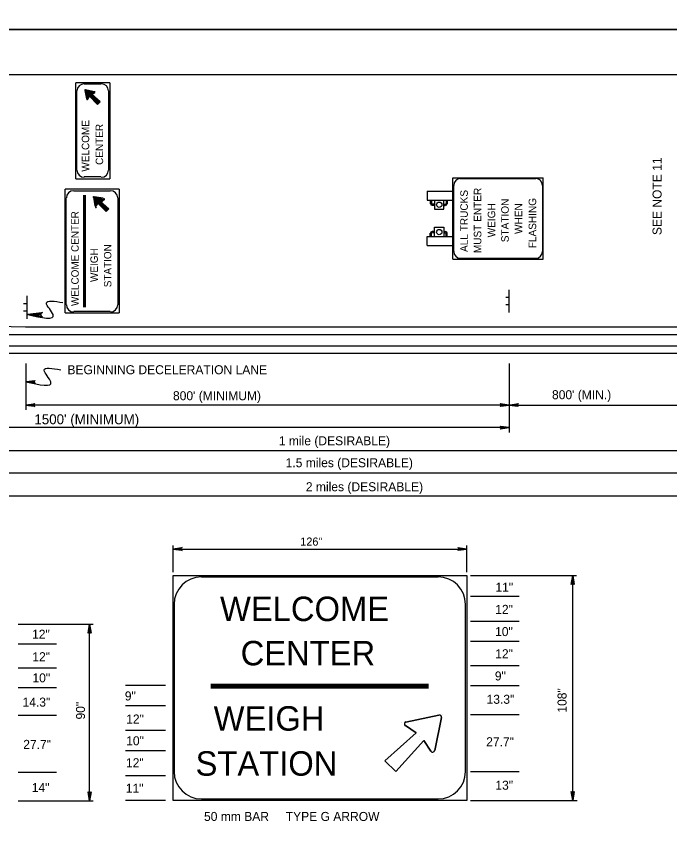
# Model space of a CAD drawing. Extents: x 2189973 to 2192941, y 2147557 to 2151454.
# Drawn here: x 2191176 to 2191890, y 2148636 to 2149520 of the extents above; entities that cross this region are included whole.
import ezdxf

# ---------------------------------------------------------------- set-up
doc = ezdxf.new("R2010")
doc.units = 0
for name, color, linetype in [('Default', 7, 'Continuous'), ('Level 2', 7, 'Continuous'), ('PLT-BNDY', 7, 'Continuous')]:
    doc.layers.add(name, color=color, linetype=linetype)

# ---------------------------------------------------------------- blocks, each defined once
blk = doc.blocks.new('RARROW')
at = {"layer": 'Default'}
blk.add_lwpolyline([(-18.156, 2.28), (-17.479, 0.966), (0, 0), (-18.156, 2.28), (-19.086, 3.077), (0, 0), (-17.465, -0.864), (-18.103, -2.164), (0, 0), (-19.086, -3.033), (-18.103, -2.164)], dxfattribs=at)

msp = doc.modelspace()

# ---------------------------------------------------------------- linework, layer by layer
at = {"layer": 'Default'}
for p, q in [((2190104.48, 2149456.38), (2192683.21, 2149456.38)), ((2191241.29, 2149342.37), (2191241.29, 2149447.36)), ((2191278.61, 2149447.36), (2191241.29, 2149447.36)), ((2191250.72, 2149446.13), (2191268.77, 2149446.13)), ((2191251.13, 2149439.57), (2191251.13, 2149439.57)), ((2191261.79, 2149437.52), (2191251.95, 2149439.57)), ((2191278.61, 2149447.36), (2191278.61, 2149342.37)), ((2191242.52, 2149351.81), (2191242.52, 2149438.34)), ((2191251.13, 2149438.75), (2191253.18, 2149429.73)), ((2191254.41, 2149429.32), (2191256.46, 2149432.6)), ((2191256.46, 2149432.6), (2191256.46, 2149432.6)), ((2191256.46, 2149432.6), (2191265.07, 2149423.57)), ((2191257.69, 2149433.42), (2191257.69, 2149433.42)), ((2191258.92, 2149434.65), (2191262.2, 2149436.7)), ((2191258.92, 2149434.65), (2191262.2, 2149436.7)), ((2191258.92, 2149434.65), (2191258.92, 2149434.65)), ((2191267.95, 2149426.44), (2191258.92, 2149434.65)), ((2191263.43, 2149437.52), (2191263.43, 2149437.52)), ((2191276.97, 2149438.34), (2191276.97, 2149351.81)), ((2191253.59, 2149428.09), (2191253.59, 2149428.09)), ((2191265.07, 2149423.57), (2191267.95, 2149426.44)), ((2191265.07, 2149423.57), (2191265.07, 2149423.57)), ((2191267.95, 2149426.44), (2191267.95, 2149426.44)), ((2191241.29, 2149342.37), (2191278.61, 2149342.37)), ((2191268.77, 2149344.42), (2191250.72, 2149344.42)), ((2191229.81, 2149195.97), (2191229.81, 2149330.89)), ((2191288.86, 2149330.89), (2191229.81, 2149330.89)), ((2191239.24, 2149329.25), (2191279.02, 2149329.25)), ((2191288.86, 2149330.89), (2191288.86, 2149195.97)), ((2191231.04, 2149204.58), (2191231.04, 2149321.46)), ((2191250.31, 2149202.12), (2191250.31, 2149324.33)), ((2191250.72, 2149202.12), (2191250.72, 2149324.33)), ((2191251.13, 2149202.12), (2191251.13, 2149324.33)), ((2191251.54, 2149202.12), (2191251.54, 2149324.33)), ((2191251.95, 2149202.12), (2191251.95, 2149324.33)), ((2191260.15, 2149323.1), (2191260.15, 2149323.1)), ((2191260.56, 2149322.28), (2191262.61, 2149312.85)), ((2191271.23, 2149321.05), (2191261.38, 2149322.69)), ((2191266.72, 2149316.54), (2191266.72, 2149316.54)), ((2191267.54, 2149315.72), (2191267.54, 2149315.72)), ((2191267.95, 2149317.77), (2191271.64, 2149319.82)), ((2191267.95, 2149317.77), (2191271.64, 2149319.82)), ((2191267.95, 2149317.77), (2191267.95, 2149317.77)), ((2191277.38, 2149309.57), (2191267.95, 2149317.77)), ((2191268.77, 2149316.95), (2191272.46, 2149319.82)), ((2191268.77, 2149316.95), (2191268.77, 2149316.95)), ((2191272.87, 2149320.64), (2191272.87, 2149320.64)), ((2191287.22, 2149321.46), (2191287.22, 2149204.58)), ((2191263.02, 2149311.21), (2191263.02, 2149311.21)), ((2191263.43, 2149312.44), (2191265.89, 2149315.31)), ((2191265.89, 2149315.31), (2191265.89, 2149315.31)), ((2191265.89, 2149315.31), (2191274.51, 2149306.69)), ((2191266.31, 2149314.49), (2191266.31, 2149314.49)), ((2191274.51, 2149306.69), (2191277.38, 2149309.57)), ((2191274.51, 2149306.69), (2191274.51, 2149306.69)), ((2191277.38, 2149309.57), (2191277.38, 2149309.57)), ((2191714.55, 2149196.38), (2191714.55, 2149220.98)), ((2191188.39, 2149189.4), (2191188.39, 2149214.42)), ((2191714.55, 2149212.78), (2191710.86, 2149212.78)), ((2191188.39, 2149205.81), (2191184.28, 2149205.81)), ((2191714.55, 2149204.58), (2191710.86, 2149204.58)), ((2191188.39, 2149197.61), (2191184.28, 2149197.61)), ((2191229.81, 2149195.97), (2191288.86, 2149195.97)), ((2191279.02, 2149197.2), (2191239.24, 2149197.2)), ((2191186.33, 2149180.79), (2191186.33, 2149180.79)), ((2191186.33, 2149180.79), (2191186.33, 2149180.79)), ((2191186.33, 2149180.79), (2192679.93, 2149180.79)), ((2190114.32, 2149172.18), (2192679.93, 2149172.18)), ((2190114.32, 2149159.88), (2192679.93, 2149159.88)), ((2190114.32, 2149151.68), (2192679.93, 2149151.68)), ((2191186.74, 2149140.6), (2191186.74, 2149089.75)), ((2191714.55, 2149140.6), (2191714.55, 2149065.14)), ((2191714.55, 2149095.08), (2191186.74, 2149095.08)), ((2191714.55, 2149095.08), (2191916.68, 2149095.08)), ((2191714.55, 2149070.47), (2190939.04, 2149070.47)), ((2190939.04, 2149045.46), (2192091.43, 2149045.46)), ((2192264.5, 2149020.85), (2190939.04, 2149020.85)), ((2192437.97, 2148995.43), (2190939.04, 2148995.43)), ((2191347.6, 2148912.43), (2191347.6, 2148941.54)), ((2191347.6, 2148937.85), (2191668.3, 2148937.85)), ((2191668.3, 2148912.43), (2191668.3, 2148941.54)), ((2191347.6, 2148908.74), (2191668.3, 2148908.74)), ((2191347.6, 2148663.08), (2191347.6, 2148908.74)), ((2191637.13, 2148907.1), (2191378.76, 2148907.1)), ((2191668.3, 2148908.74), (2191668.3, 2148663.08)), ((2191672.4, 2148908.74), (2191705.21, 2148908.74)), ((2191672.4, 2148908.74), (2191705.21, 2148908.74)), ((2191694.54, 2148908.74), (2191788.05, 2148908.74)), ((2191783.95, 2148663.08), (2191783.95, 2148908.74)), ((2191672.4, 2148886.18), (2191725.51, 2148886.18)), ((2191348.83, 2148877.16), (2191348.83, 2148694.66)), ((2191667.07, 2148694.66), (2191667.07, 2148877.16)), ((2191672.4, 2148859.11), (2191725.51, 2148859.11)), ((2191178.57, 2148855.56), (2191260.5, 2148855.56)), ((2191256.4, 2148662.82), (2191256.4, 2148855.56)), ((2191178.57, 2148834.24), (2191220.39, 2148834.24)), ((2191672.4, 2148836.97), (2191725.51, 2148836.97)), ((2191178.57, 2148807.99), (2191220.39, 2148807.99)), ((2191672.4, 2148810.72), (2191725.51, 2148810.72)), ((2191178.57, 2148786.67), (2191220.39, 2148786.67)), ((2191339.29, 2148788.58), (2191295.64, 2148788.58)), ((2191389.02, 2148790.22), (2191626.47, 2148790.22)), ((2191389.02, 2148789.4), (2191626.47, 2148789.4)), ((2191389.02, 2148788.58), (2191626.47, 2148788.58)), ((2191389.02, 2148787.75), (2191626.47, 2148787.75)), ((2191389.02, 2148786.93), (2191626.47, 2148786.93)), ((2191389.02, 2148786.11), (2191626.47, 2148786.11)), ((2191672.4, 2148788.58), (2191725.51, 2148788.58)), ((2191339.29, 2148766.43), (2191295.64, 2148766.43)), ((2191178.57, 2148756.32), (2191220.39, 2148756.32)), ((2191637.95, 2148756.18), (2191601.86, 2148748.79)), ((2191601.86, 2148748.79), (2191637.95, 2148756.18)), ((2191633.44, 2148717.63), (2191640.82, 2148753.72)), ((2191640.82, 2148753.72), (2191633.44, 2148717.63)), ((2191641.64, 2148757), (2191641.64, 2148757)), ((2191672.4, 2148757), (2191725.51, 2148757)), ((2191596.53, 2148747.97), (2191596.53, 2148747.97)), ((2191601.45, 2148745.1), (2191612.93, 2148736.9)), ((2191612.93, 2148736.9), (2191601.45, 2148745.1)), ((2191339.29, 2148739.36), (2191295.64, 2148739.36)), ((2191612.93, 2148736.9), (2191578.89, 2148706.55)), ((2191578.89, 2148706.55), (2191612.93, 2148736.9)), ((2191612.93, 2148736.9), (2191578.89, 2148706.55)), ((2191578.89, 2148706.55), (2191612.93, 2148736.9)), ((2191612.93, 2148736.9), (2191612.93, 2148736.9)), ((2191612.93, 2148736.9), (2191612.93, 2148736.9)), ((2191617.03, 2148733.21), (2191617.03, 2148733.21)), ((2191617.03, 2148733.21), (2191617.03, 2148733.21)), ((2191590.79, 2148694.66), (2191621.54, 2148728.7)), ((2191621.54, 2148728.7), (2191590.79, 2148694.66)), ((2191621.54, 2148728.7), (2191621.54, 2148728.7)), ((2191621.54, 2148728.7), (2191621.54, 2148728.7)), ((2191621.54, 2148728.7), (2191628.93, 2148716.81)), ((2191628.93, 2148716.81), (2191621.54, 2148728.7)), ((2191339.29, 2148717.22), (2191295.64, 2148717.22)), ((2191578.89, 2148706.55), (2191578.89, 2148706.55)), ((2191578.89, 2148706.55), (2191578.89, 2148706.55)), ((2191578.89, 2148706.55), (2191590.79, 2148694.66)), ((2191590.79, 2148694.66), (2191578.89, 2148706.55)), ((2191631.8, 2148712.3), (2191631.8, 2148712.3)), ((2191178.57, 2148693.98), (2191220.39, 2148693.98)), ((2191339.29, 2148690.15), (2191295.64, 2148690.15)), ((2191590.79, 2148694.66), (2191590.79, 2148694.66)), ((2191590.79, 2148694.66), (2191590.79, 2148694.66)), ((2191672.4, 2148694.66), (2191725.51, 2148694.66)), ((2191178.57, 2148662.82), (2191260.5, 2148662.82)), ((2191339.29, 2148663.08), (2191295.64, 2148663.08)), ((2191668.3, 2148663.08), (2191347.6, 2148663.08)), ((2191378.76, 2148664.72), (2191637.13, 2148664.72)), ((2191672.4, 2148663.08), (2191788.96, 2148663.08))]:
    msp.add_line(p, q, dxfattribs=at)
for points in [[(2191267.54, 2149426.44), (2191265.07, 2149423.98), (2191256.46, 2149433.01), (2191254.41, 2149429.73), (2191254, 2149429.73), (2191253.59, 2149429.73), (2191251.54, 2149438.75), (2191251.95, 2149439.16), (2191262.2, 2149437.11), (2191258.51, 2149434.65), (2191267.54, 2149426.44), (2191265.07, 2149424.39), (2191256.46, 2149433.01), (2191254, 2149430.14), (2191254, 2149429.73), (2191251.95, 2149438.75), (2191261.79, 2149437.11), (2191258.51, 2149434.65), (2191267.13, 2149426.44), (2191265.48, 2149424.8), (2191256.46, 2149433.42), (2191254, 2149430.55), (2191252.36, 2149438.34), (2191260.97, 2149436.7), (2191257.69, 2149434.65), (2191266.72, 2149426.44), (2191265.48, 2149425.21), (2191256.46, 2149433.42), (2191254.41, 2149430.96), (2191252.77, 2149437.93), (2191260.15, 2149436.7), (2191257.69, 2149434.65), (2191266.31, 2149426.44), (2191265.48, 2149425.62), (2191256.46, 2149433.83), (2191254.82, 2149431.78), (2191253.59, 2149437.52), (2191259.74, 2149436.29), (2191256.87, 2149434.65), (2191265.89, 2149426.44), (2191265.48, 2149426.44), (2191256.46, 2149434.24), (2191254.82, 2149432.6), (2191254, 2149437.11), (2191258.92, 2149436.29), (2191256.87, 2149434.65), (2191265.89, 2149426.86), (2191265.48, 2149426.44), (2191265.48, 2149426.03), (2191256.46, 2149434.65), (2191265.48, 2149426.86), (2191265.07, 2149426.44), (2191256.46, 2149434.65), (2191255.23, 2149433.42), (2191254.41, 2149436.7), (2191258.1, 2149435.88), (2191255.64, 2149434.24), (2191254.82, 2149436.29), (2191257.69, 2149435.88), (2191256.05, 2149434.65), (2191255.64, 2149436.29), (2191256.87, 2149435.88), (2191256.05, 2149435.47), (2191256.05, 2149435.88), (2191256.46, 2149435.88)], [(2191276.97, 2149309.98), (2191274.51, 2149307.51), (2191265.89, 2149315.72), (2191263.43, 2149312.85), (2191263.02, 2149312.44), (2191262.61, 2149312.85), (2191260.97, 2149322.28), (2191261.38, 2149322.69), (2191271.64, 2149320.23), (2191267.54, 2149317.77), (2191276.97, 2149309.98), (2191274.51, 2149307.92), (2191265.89, 2149316.13), (2191263.43, 2149312.85), (2191263.43, 2149312.85), (2191261.38, 2149322.28), (2191270.82, 2149320.23), (2191267.54, 2149317.36), (2191276.56, 2149309.98), (2191274.51, 2149308.33), (2191265.89, 2149316.54), (2191263.43, 2149313.26), (2191261.79, 2149321.87), (2191270.41, 2149320.23), (2191266.72, 2149317.36), (2191276.15, 2149309.98), (2191274.92, 2149308.75), (2191265.89, 2149316.54), (2191263.84, 2149314.08), (2191262.2, 2149321.46), (2191269.18, 2149319.82), (2191266.72, 2149317.36), (2191275.74, 2149309.98), (2191274.92, 2149309.16), (2191265.89, 2149316.95), (2191264.25, 2149314.9), (2191262.61, 2149321.05), (2191268.36, 2149319.82), (2191266.31, 2149317.36), (2191275.33, 2149309.98), (2191274.92, 2149309.57), (2191265.89, 2149317.36), (2191264.25, 2149315.72), (2191263.43, 2149320.64), (2191267.95, 2149319.82), (2191265.89, 2149317.36), (2191274.92, 2149309.98), (2191274.92, 2149309.57), (2191274.92, 2149309.57), (2191265.89, 2149317.36), (2191274.92, 2149309.98), (2191274.51, 2149309.57), (2191265.89, 2149317.36), (2191264.66, 2149316.13), (2191263.84, 2149320.23), (2191267.13, 2149319.41), (2191265.07, 2149316.95), (2191264.25, 2149319.82), (2191266.72, 2149319.41), (2191265.07, 2149317.77), (2191264.66, 2149319.41), (2191265.89, 2149319.41), (2191265.48, 2149318.59), (2191265.07, 2149319.41), (2191265.89, 2149319)], [(2191203.97, 2149192.28), (2191203.56, 2149193.51), (2191189.21, 2149193.92), (2191203.97, 2149192.28), (2191205.2, 2149191.46), (2191189.21, 2149193.92), (2191203.56, 2149194.74), (2191203.97, 2149195.97), (2191189.21, 2149193.92), (2191205.2, 2149196.38), (2191203.97, 2149195.97)]]:
    msp.add_lwpolyline(points, dxfattribs=at)
for centre, radius, start, end in [((2191297.63, 2153881.5), 4702.16, 265.6447, 268.64351), ((2191378.63, 2148877.35), 30, 90, 180), ((2191636.94, 2148877.35), 30, 0, 90), ((2191638.49, 2148754.2), 2.25, 348.26016, 101.73982), ((2191638.49, 2148754.2), 2.25, 348.26016, 101.73982), ((2191602.35, 2148746.69), 2.25, 101.73984, 236.68377), ((2191602.35, 2148746.69), 2.25, 101.73984, 236.68377), ((2191630.98, 2148718.06), 2.25, 213.31623, 348.26016), ((2191630.98, 2148718.06), 2.25, 213.31623, 348.26016), ((2191378.63, 2148694.75), 30, 180, 270), ((2191636.94, 2148694.75), 30, 270, 0)]:
    msp.add_arc(centre, radius, start, end, dxfattribs=at)
for centre, major_axis, start_param, end_param in [((2191250.71, 2149438.45), (-8.16, 0), 4.712389, 6.283185), ((2191251.81, 2149439.09), (-0.619, 0), 4.50749, 6.488084), ((2191269.02, 2149438.45), (8.16, 0), 0, 1.570796), ((2191261.75, 2149437.13), (0.619, 0), 5.293867, 7.649083), ((2191253.87, 2149429.65), (0.619, 0), 3.346491, 5.701707), ((2191250.71, 2149351.83), (-8.16, 0), 0, 1.570796), ((2191269.02, 2149351.83), (8.16, 0), 4.712389, 6.283185), ((2191239.23, 2149321.58), (-8.12, 0), 4.712389, 6.283185), ((2191279.18, 2149321.58), (8.12, 0), 0, 1.570796), ((2191261.07, 2149322.22), (-0.619, 0), 4.50749, 6.488084), ((2191261.15, 2149322.14), (-0.688, 0), 4.50749, 6.488084), ((2191271.01, 2149320.26), (0.619, 0), 5.293867, 7.649083), ((2191272.19, 2149319.96), (0.688, 0), 5.293867, 7.649083), ((2191263.14, 2149312.78), (0.619, 0), 3.346491, 5.701707), ((2191263.44, 2149311.65), (0.688, 0), 3.346491, 5.701707), ((2191239.23, 2149204.65), (-8.12, 0), 0, 1.570796), ((2191279.18, 2149204.65), (8.12, 0), 4.712389, 6.283185)]:
    msp.add_ellipse(centre, major_axis=major_axis, ratio=0.95, start_param=start_param, end_param=end_param, dxfattribs=at)
for points in [[(2191189.21, 2149193.92), (2191216.68, 2149193.92), (2191209.3, 2149206.63), (2191227.35, 2149207.04)], [(2191186.74, 2149120.51), (2191214.22, 2149120.51), (2191206.84, 2149133.22), (2191224.88, 2149133.63)]]:
    msp.add_spline(points, degree=3, dxfattribs=at)
at = {"layer": 'Level 2'}
for p, q in [((2191653.03, 2149254.61), (2191653.03, 2149343.6)), ((2191653.03, 2149343.6), (2191751.87, 2149343.6)), ((2191661.24, 2149342.78), (2191743.67, 2149342.78)), ((2191751.87, 2149254.61), (2191751.87, 2149343.6)), ((2191654.26, 2149262.81), (2191654.26, 2149335.4)), ((2191751.05, 2149335.4), (2191751.05, 2149262.81)), ((2191625.15, 2149328.84), (2191625.15, 2149319)), ((2191625.15, 2149328.84), (2191653.03, 2149328.84)), ((2191625.15, 2149319), (2191632.94, 2149319)), ((2191628.43, 2149319), (2191628.43, 2149314.9)), ((2191629.66, 2149319), (2191629.66, 2149314.9)), ((2191632.94, 2149319), (2191632.94, 2149309.16)), ((2191632.94, 2149319), (2191653.03, 2149319)), ((2191643.19, 2149309.16), (2191643.19, 2149319)), ((2191645.65, 2149319), (2191645.65, 2149314.9)), ((2191646.88, 2149319), (2191646.88, 2149314.9)), ((2191632.94, 2149314.49), (2191630.89, 2149314.49)), ((2191632.94, 2149313.26), (2191630.89, 2149313.26)), ((2191632.94, 2149309.16), (2191643.19, 2149309.16)), ((2191643.19, 2149314.49), (2191644.83, 2149314.49)), ((2191643.19, 2149313.26), (2191644.83, 2149313.26)), ((2191632.94, 2149279.22), (2191632.94, 2149289.47)), ((2191632.94, 2149289.47), (2191643.19, 2149289.47)), ((2191643.19, 2149289.47), (2191643.19, 2149279.22)), ((2191628.43, 2149279.22), (2191628.43, 2149282.91)), ((2191629.66, 2149279.22), (2191629.66, 2149282.91)), ((2191632.94, 2149284.96), (2191630.89, 2149284.96)), ((2191632.94, 2149283.32), (2191630.89, 2149283.32)), ((2191643.19, 2149284.96), (2191644.83, 2149284.96)), ((2191643.19, 2149283.32), (2191644.83, 2149283.32)), ((2191645.65, 2149279.22), (2191645.65, 2149282.91)), ((2191646.88, 2149279.22), (2191646.88, 2149282.91)), ((2191625.15, 2149269.38), (2191625.15, 2149279.22)), ((2191625.15, 2149279.22), (2191632.94, 2149279.22)), ((2191632.94, 2149279.22), (2191653.03, 2149279.22)), ((2191625.15, 2149269.38), (2191653.03, 2149269.38)), ((2191653.03, 2149254.61), (2191751.87, 2149254.61)), ((2191743.67, 2149255.43), (2191661.24, 2149255.43))]:
    msp.add_line(p, q, dxfattribs=at)
for centre in [(2191638.26, 2149314), (2191638.26, 2149284.13)]:
    msp.add_circle(centre, 2.92, dxfattribs=at)
for centre, radius, start, end in [((2191661.5, 2149335.22), 7.4, 90, 180), ((2191743.57, 2149335.22), 7.4, 360, 90), ((2191630.51, 2149315.25), 1.83, 180, 270), ((2191630.51, 2149315.25), 0.666, 180, 270), ((2191645.08, 2149315.25), 0.666, 270, 360), ((2191645.08, 2149315.25), 1.83, 270, 360), ((2191630.51, 2149282.88), 1.83, 90, 180), ((2191630.51, 2149282.88), 0.666, 90, 180), ((2191645.08, 2149282.88), 1.83, 360, 90), ((2191645.08, 2149282.88), 0.666, 360, 90), ((2191661.5, 2149262.92), 7.4, 180, 270), ((2191743.57, 2149262.92), 7.4, 270, 360)]:
    msp.add_arc(centre, radius, start, end, dxfattribs=at)
at = {"layer": 'PLT-BNDY'}
for points in [[(2189973.25, 2151454.41), (2192732.43, 2151454.41), (2192732.43, 2149505.6), (2189973.25, 2149505.6)], [(2189973.25, 2149505.6), (2192732.43, 2149505.6), (2192732.43, 2147556.78), (2189973.25, 2147556.78)]]:
    msp.add_lwpolyline(points, close=True, dxfattribs=at)

# ---------------------------------------------------------------- block references
at = {"layer": 'Default', "xscale": 0.515679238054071, "yscale": 0.5369477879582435}
for p, rotation in [((2191187.3, 2149120.51), 180), ((2191186.74, 2149095.08), 180), ((2191714.55, 2149095.08), 180), ((2191347.59, 2148937.85), 180), ((2191783.95, 2148908.74), 89.99999999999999), ((2191256.4, 2148855.56), 89.99999999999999), ((2191256.4, 2148662.82), -90.00000000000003), ((2191783.95, 2148663.08), -90.00000000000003)]:
    msp.add_blockref('RARROW', p, dxfattribs=dict(at, rotation=rotation))
for p in [(2191714.55, 2149095.08), (2191714.55, 2149070.47), (2191668.3, 2148937.85)]:
    msp.add_blockref('RARROW', p, dxfattribs=at)

# ---------------------------------------------------------------- texts
at = {"layer": 'Default'}
for s, height, rotation, p in [('WELCOME', 8.162, 90, (2191256.05, 2149350.17)), ('CENTER', 8.162, 90, (2191271.23, 2149357.55)), ('SEE NOTE 11', 9.8425, 90, (2191881.02, 2149280.84)), ('WELCOME CENTER', 8.1127, 90, (2191244.57, 2149203.35)), ('WEIGH', 8.113, 90, (2191265.48, 2149229.59)), ('STATION', 8.113, 90, (2191280.25, 2149223.85)), ('WELCOME', 26.717, 360, (2191398.86, 2148859.11)), ('CENTER', 26.717, 360, (2191421.41, 2148810.72)), (' 108"', 9.842, 90, (2191777.25, 2148755.4)), ('90"', 9.842, 90, (2191251.46, 2148751.56)), ('WEIGH', 26.717, 360, (2191391.89, 2148739.36)), ('STATION', 26.717, 360, (2191372.2, 2148690.15))]:
    msp.add_text(s, height=height, rotation=rotation, dxfattribs=at).set_placement(p)
for s, height, p in [('BEGINNING DECELERATION LANE', 9.8425, (2191232.27, 2149128.82)), ("800' (MINIMUM)", 9.8425, (2191347.51, 2149100.41)), ("800' (MIN.)", 9.8425, (2191761.37, 2149101.52)), ("1500' (MINIMUM)", 10.8883, (2191196.18, 2149074.17)), (' 1 mile (DESIRABLE)', 9.8425, (2191459.46, 2149051.2)), ('1.5 miles (DESIRABLE)', 9.8425, (2191470.54, 2149027.21)), ('2 miles (DESIRABLE)', 9.8425, (2191492.62, 2149000.96)), ('126"', 8.858, (2191486.54, 2148941.53)), ('11"', 9.842, (2191699.59, 2148891.14)), ('12"', 9.842, (2191699.38, 2148866.95)), ('12"', 9.842, (2191193.66, 2148839.84)), ('10"', 9.842, (2191699.23, 2148842.71)), ('12"', 9.842, (2191193.95, 2148815.23)), ('12"', 9.842, (2191699.38, 2148818.48)), (' 9"', 9.842, (2191695.29, 2148794.24)), ('10"', 9.842, (2191194.09, 2148792.14)), (' 9"', 9.842, (2191291.25, 2148772.38)), ('13.3"', 9.842, (2191689.93, 2148768.71)), ('14.3"', 9.842, (2191183.25, 2148765.65)), ('12"', 9.842, (2191296.43, 2148747.15)), ('10"', 9.842, (2191296.43, 2148723.38)), ('27.7"', 9.842, (2191184.05, 2148719.43)), ('27.7"', 9.842, (2191689.53, 2148722.33)), ('12"', 9.842, (2191296.22, 2148699.38)), ('14"', 9.842, (2191193.32, 2148672.27)), ('11"', 9.842, (2191295.98, 2148671.49)), ('13"', 9.842, (2191699.54, 2148674.83)), ('50 mm BAR     TYPE G ARROW', 9.8425, (2191381.41, 2148640.7))]:
    msp.add_text(s, height=height, dxfattribs=at).set_placement(p)
at = {"layer": 'Level 2'}
for s, p in [('ALL TRUCKS', (2191669.44, 2149262.4)), ('MUST ENTER', (2191684.2, 2149261.17)), ('STATION', (2191714.14, 2149273.07)), ('FLASHING', (2191744.08, 2149266.5)), ('WEIGH', (2191699.38, 2149278.4)), ('WHEN', (2191728.9, 2149282.09))]:
    msp.add_text(s, height=8.216, rotation=90, dxfattribs=at).set_placement(p)

doc.saveas('drawing.dxf')
